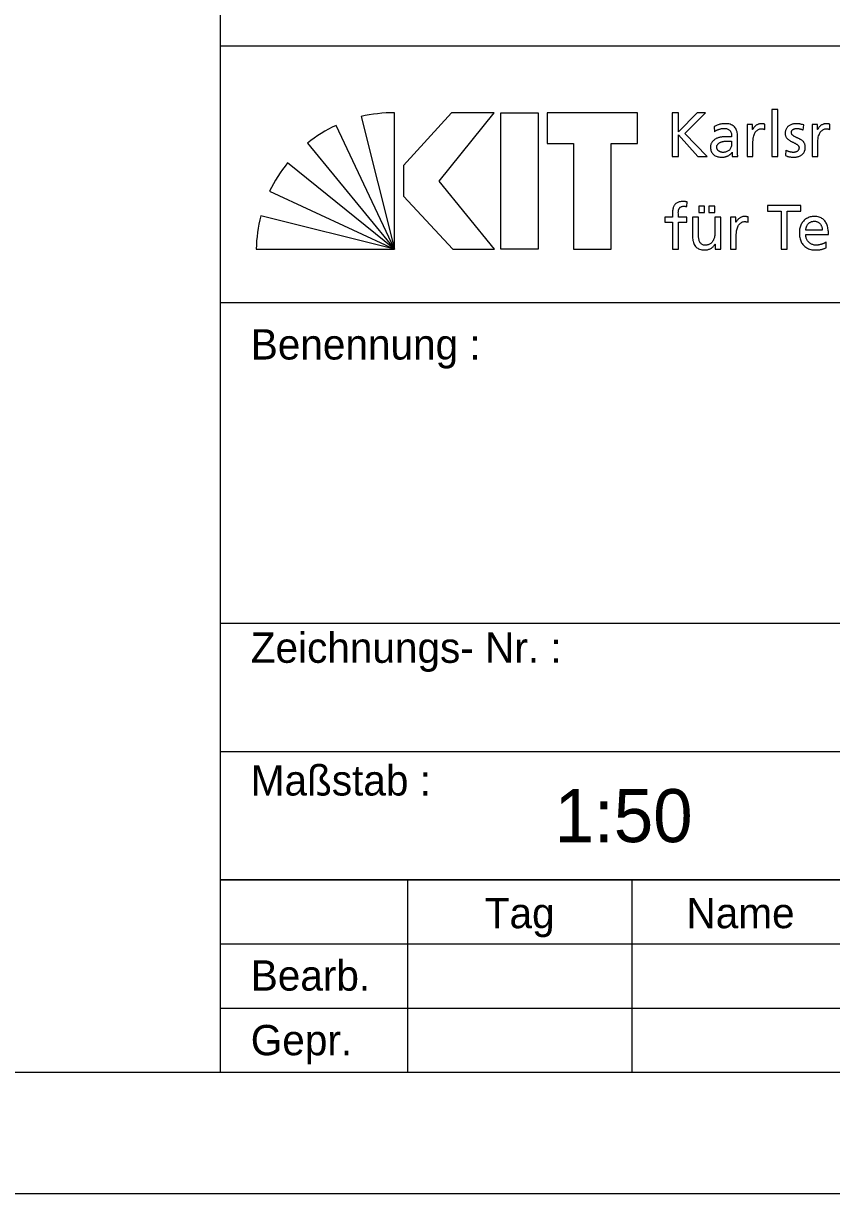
# Model space of a CAD drawing. Extents: x 0 to 21, y 0 to 14.9.
# Drawn here: x 15.75 to 18.416, y 0 to 3.858 of the extents above; entities that cross this region are included whole.
import ezdxf

# ---------------------------------------------------------------- set-up
doc = ezdxf.new("R2010")
doc.units = 0
doc.layers.add('90_Plankopf', color=7, linetype='Continuous')

msp = doc.modelspace()

# ---------------------------------------------------------------- linework, layer by layer
at = {"layer": '90_Plankopf'}
for p, q in [((16.4001, 3.784), (16.4001, 4.4185)), ((16.4001, 3.784), (20.6001, 3.784)), ((16.8638, 3.5511), (16.9741, 3.1138)), ((16.9741, 3.1138), (16.9741, 3.5637)), ((17.8905, 3.5638), (17.8905, 3.4198)), ((16.9741, 3.1138), (16.7817, 3.5221)), ((18.029, 3.5176), (18.03, 3.5011)), ((18.1964, 3.5087), (18.1964, 3.5261)), ((18.3229, 3.5065), (18.3245, 3.5234)), ((18.4106, 3.5087), (18.4106, 3.5261)), ((18.106, 3.4404), (18.106, 3.484)), ((16.6872, 3.4638), (16.9741, 3.1138)), ((18.0866, 3.4699), (18.0866, 3.4606)), ((18.2649, 3.4404), (18.2639, 3.4231)), ((16.9741, 3.1138), (16.6217, 3.3988)), ((17.8905, 3.4198), (17.9112, 3.4198)), ((17.9753, 3.4198), (18.0055, 3.4198)), ((16.562, 3.3052), (16.9741, 3.1138)), ((17.9387, 3.2541), (17.9395, 3.2698)), ((16.9741, 3.1138), (16.5329, 3.2239)), ((18.1414, 3.2027), (18.1414, 3.2201)), ((18.3854, 3.1765), (18.3309, 3.1765)), ((18.3309, 3.1621), (18.406, 3.1621)), ((18.3979, 3.1182), (18.3979, 3.1375)), ((16.5183, 3.1138), (16.9741, 3.1138)), ((16.4001, 2.938), (20.6001, 2.938)), ((16.4001, 1.8805), (20.6001, 1.8805)), ((16.4001, 1.4575), (20.6001, 1.4575)), ((16.4001, 1.0345), (20.6001, 1.0345)), ((16.4001, 1.0345), (20.6001, 1.0345)), ((16.4001, 1.0345), (20.6001, 1.0345)), ((16.4001, 1.0345), (20.6001, 1.0345)), ((16.4001, 0.4), (16.4001, 1.0345)), ((17.0177, 1.0345), (17.0177, 0.4)), ((17.7589, 0.4), (17.7589, 1.0345)), ((16.4001, 0.823), (18.5001, 0.823)), ((16.4001, 0.6115), (18.5001, 0.6115)), ((16.4001, 0.4), (20.6001, 0.4)), ((16.4001, 0.4), (20.6, 0.4))]:
    msp.add_line(p, q, dxfattribs=at)
for points in [[(0, 0), (21, 0), (21, 14.85), (0, 14.85)], [(0.4, 0.4), (20.6, 0.4), (20.6, 14.45), (0.4, 14.45)], [(17.3034, 3.5638), (17.1619, 3.5638), (17.0037, 3.3894), (17.0037, 3.2891), (17.1669, 3.1138), (17.3043, 3.1138), (17.1212, 3.3376)], [(17.4486, 3.5638), (17.4486, 3.1138), (17.3251, 3.1138), (17.3251, 3.5638)], [(17.4782, 3.5638), (17.4782, 3.4625), (17.5651, 3.4625), (17.5651, 3.1138), (17.6886, 3.1138), (17.6886, 3.4625), (17.7755, 3.4625), (17.7755, 3.5638)]]:
    msp.add_lwpolyline(points, close=True, dxfattribs=at)
for points in [[(16.4001, 1.0345), (16.4001, 3.784)], [(18.0055, 3.4198), (17.9324, 3.4957), (18.0001, 3.5638), (17.9726, 3.5638), (17.9112, 3.5005), (17.9112, 3.5638), (17.8905, 3.5638)], [(18.2191, 3.4198), (18.2385, 3.4198), (18.2385, 3.5745), (18.2191, 3.5745), (18.2191, 3.4198)], [(18.1561, 3.5087), (18.1557, 3.5087), (18.1557, 3.525), (18.1376, 3.525), (18.1376, 3.4198), (18.157, 3.4198), (18.157, 3.4677)], [(18.3704, 3.5087), (18.37, 3.5087), (18.37, 3.525), (18.3518, 3.525), (18.3518, 3.4198), (18.3712, 3.4198), (18.3712, 3.4677)], [(17.9112, 3.4198), (17.9112, 3.4904), (17.9753, 3.4198)], [(18.0882, 3.4334), (18.0886, 3.4334), (18.0886, 3.4198), (18.1068, 3.4198)], [(17.9778, 3.2558), (17.9778, 3.2351), (17.9972, 3.2351), (17.9972, 3.2558), (17.9778, 3.2558)], [(18.0116, 3.2558), (18.0116, 3.2351), (18.031, 3.2351), (18.031, 3.2558), (18.0116, 3.2558)], [(18.2496, 3.1138), (18.2702, 3.1138), (18.2702, 3.2397), (18.315, 3.2397), (18.315, 3.2578), (18.2048, 3.2578), (18.2048, 3.2397), (18.2496, 3.2397), (18.2496, 3.1138)], [(17.8913, 3.2288), (17.8913, 3.2191), (17.8665, 3.2191), (17.8665, 3.2034), (17.8913, 3.2034), (17.8913, 3.1138), (17.9107, 3.1138), (17.9107, 3.2034), (17.9385, 3.2034), (17.9385, 3.2191), (17.9107, 3.2191), (17.9107, 3.2304)], [(17.9771, 3.1646), (17.9771, 3.2191), (17.9577, 3.2191), (17.9577, 3.1565)], [(18.0508, 3.1138), (18.0508, 3.2191), (18.0314, 3.2191), (18.0314, 3.1704)], [(18.1012, 3.2027), (18.1008, 3.2027), (18.1008, 3.2191), (18.0826, 3.2191), (18.0826, 3.1138), (18.102, 3.1138), (18.102, 3.1617)], [(18.0316, 3.1305), (18.032, 3.1305), (18.032, 3.1138), (18.0508, 3.1138)], [(20.6001, 1.0345), (16.4001, 1.0345)], [(16.4001, 1.0345), (16.4001, 1.0345)], [(16.4001, 0.4), (20.6001, 0.4)]]:
    msp.add_lwpolyline(points, dxfattribs=at)
for centre, start, end in [((16.9725, 3.0873), 89.8053, 103.1895), ((16.9831, 3.0904), 115.0126, 128.3968), ((16.9909, 3.0976), 140.7898, 154.174), ((16.9946, 3.1064), 165.7222, 179.1064)]:
    msp.add_arc(centre, 0.4764, start, end, dxfattribs=at)
for points in [[(18.106, 3.484), (18.106, 3.4935), (18.1046, 3.5015), (18.1017, 3.508), (18.0988, 3.5145), (18.0942, 3.5193), (18.088, 3.5226), (18.0818, 3.5258), (18.0737, 3.5275), (18.0637, 3.5275), (18.057, 3.5275), (18.0507, 3.5265), (18.0449, 3.5247), (18.0391, 3.5229), (18.0338, 3.5206), (18.029, 3.5176)], [(18.03, 3.5011), (18.0327, 3.5033), (18.0357, 3.5052), (18.039, 3.5068), (18.0423, 3.5084), (18.0459, 3.5096), (18.0495, 3.5105), (18.0532, 3.5114), (18.0569, 3.5118), (18.0606, 3.5118), (18.067, 3.5118), (18.0721, 3.5108), (18.0759, 3.5088), (18.0798, 3.5067), (18.0825, 3.5036), (18.0841, 3.4996), (18.0858, 3.4955), (18.0866, 3.4904), (18.0866, 3.4844)], [(18.1964, 3.5261), (18.195, 3.5263), (18.1937, 3.5266), (18.1925, 3.5268), (18.1913, 3.527), (18.1899, 3.5272), (18.1885, 3.5273), (18.1871, 3.5274), (18.1855, 3.5275), (18.1836, 3.5275), (18.1798, 3.5275), (18.1762, 3.5267), (18.1726, 3.5251), (18.1691, 3.5235), (18.1659, 3.5213), (18.1631, 3.5184), (18.1602, 3.5156), (18.1579, 3.5124), (18.1561, 3.5087)], [(18.3245, 3.5234), (18.3208, 3.5245), (18.3169, 3.5255), (18.313, 3.5263), (18.3091, 3.5271), (18.3049, 3.5275), (18.3004, 3.5275), (18.2952, 3.5275), (18.2903, 3.5268), (18.2858, 3.5255), (18.2813, 3.5242), (18.2774, 3.5222), (18.274, 3.5195), (18.2707, 3.5168), (18.268, 3.5135), (18.2661, 3.5094), (18.2643, 3.5053), (18.2633, 3.5006), (18.2633, 3.4951), (18.2633, 3.4909), (18.2642, 3.4873), (18.2658, 3.4842), (18.2674, 3.4811), (18.2696, 3.4785), (18.2723, 3.4762), (18.275, 3.474), (18.278, 3.472), (18.2812, 3.4702), (18.2844, 3.4685), (18.2877, 3.4669), (18.2909, 3.4654), (18.2942, 3.4638), (18.2971, 3.4622), (18.2998, 3.4606), (18.3025, 3.459), (18.3047, 3.4572), (18.3064, 3.4551), (18.308, 3.4531), (18.3088, 3.4508), (18.3089, 3.4481), (18.3088, 3.4452), (18.3082, 3.4429), (18.307, 3.4409), (18.3058, 3.439), (18.3043, 3.4374), (18.3023, 3.4363), (18.3003, 3.4351), (18.2982, 3.4343), (18.2959, 3.4338), (18.2936, 3.4332), (18.2913, 3.433), (18.2891, 3.433), (18.2871, 3.433), (18.2848, 3.4333), (18.282, 3.4338), (18.2792, 3.4344), (18.2763, 3.4352), (18.2733, 3.4363), (18.2703, 3.4374), (18.2675, 3.4388), (18.2649, 3.4404)], [(18.2639, 3.4231), (18.2684, 3.4208), (18.273, 3.4192), (18.2779, 3.4184), (18.2828, 3.4176), (18.2878, 3.4172), (18.2928, 3.4173), (18.2975, 3.4173), (18.3021, 3.418), (18.3064, 3.4193), (18.3108, 3.4206), (18.3147, 3.4226), (18.3182, 3.4253), (18.3216, 3.428), (18.3244, 3.4314), (18.3264, 3.4355), (18.3284, 3.4396), (18.3295, 3.4445), (18.3295, 3.4501), (18.3295, 3.4549), (18.3286, 3.459), (18.327, 3.4623), (18.3253, 3.4656), (18.3232, 3.4685), (18.3205, 3.4708), (18.3178, 3.4731), (18.3148, 3.4751), (18.3115, 3.4767), (18.3083, 3.4784), (18.3051, 3.4799), (18.3018, 3.4813), (18.2986, 3.4828), (18.2956, 3.4843), (18.2929, 3.4858), (18.2902, 3.4874), (18.2881, 3.4892), (18.2864, 3.4913), (18.2848, 3.4934), (18.2839, 3.496), (18.2839, 3.499), (18.2839, 3.5019), (18.2848, 3.5043), (18.2865, 3.5062), (18.2882, 3.5081), (18.2905, 3.5095), (18.2933, 3.5104), (18.296, 3.5114), (18.2991, 3.5118), (18.3025, 3.5118), (18.3036, 3.5118), (18.3052, 3.5116), (18.307, 3.5114), (18.3088, 3.5111), (18.3107, 3.5106), (18.3128, 3.5101), (18.3148, 3.5096), (18.3167, 3.5091), (18.3185, 3.5084), (18.3203, 3.5078), (18.3218, 3.5071), (18.3229, 3.5065)], [(18.4106, 3.5261), (18.4093, 3.5263), (18.408, 3.5266), (18.4068, 3.5268), (18.4055, 3.527), (18.4042, 3.5272), (18.4028, 3.5273), (18.4014, 3.5274), (18.3997, 3.5275), (18.3978, 3.5275), (18.3941, 3.5275), (18.3904, 3.5267), (18.3869, 3.5251), (18.3834, 3.5235), (18.3802, 3.5213), (18.3773, 3.5184), (18.3744, 3.5156), (18.3721, 3.5124), (18.3704, 3.5087)], [(18.0866, 3.4844), (18.0841, 3.4845), (18.0817, 3.4846), (18.0795, 3.4846), (18.0773, 3.4847), (18.0752, 3.4848), (18.073, 3.4848), (18.0708, 3.4848), (18.0685, 3.4848), (18.0659, 3.4848), (18.0619, 3.4848), (18.0576, 3.4844), (18.0532, 3.4837), (18.0487, 3.483), (18.0443, 3.4818), (18.0401, 3.4802), (18.0358, 3.4786), (18.032, 3.4764), (18.0285, 3.4737), (18.025, 3.4711), (18.0223, 3.4678), (18.0202, 3.4639), (18.0181, 3.46), (18.0171, 3.4554), (18.017, 3.4501), (18.0171, 3.4425), (18.0188, 3.4363), (18.022, 3.4314), (18.0253, 3.4266), (18.0298, 3.423), (18.0355, 3.4207), (18.0413, 3.4184), (18.048, 3.4173), (18.0556, 3.4173), (18.0601, 3.4173), (18.064, 3.4179), (18.0676, 3.4189), (18.0711, 3.42), (18.0742, 3.4213), (18.0769, 3.4229), (18.0796, 3.4246), (18.0818, 3.4264), (18.0837, 3.4282), (18.0856, 3.43), (18.0871, 3.4317), (18.0882, 3.4334)], [(18.157, 3.4677), (18.157, 3.4765), (18.1582, 3.4841), (18.1605, 3.4905), (18.1629, 3.4969), (18.1662, 3.5019), (18.1705, 3.5053), (18.1748, 3.5088), (18.1798, 3.5105), (18.1856, 3.5106), (18.1873, 3.5106), (18.1891, 3.5105), (18.1909, 3.5102), (18.1928, 3.5099), (18.1946, 3.5094), (18.1964, 3.5087)], [(18.3712, 3.4677), (18.3712, 3.4765), (18.3724, 3.4841), (18.3748, 3.4905), (18.3772, 3.4969), (18.3805, 3.5019), (18.3847, 3.5053), (18.389, 3.5088), (18.3941, 3.5105), (18.3999, 3.5106), (18.4016, 3.5106), (18.4033, 3.5105), (18.4052, 3.5102), (18.407, 3.5099), (18.4088, 3.5094), (18.4106, 3.5087)], [(18.0866, 3.4606), (18.0866, 3.4554), (18.0855, 3.4506), (18.0832, 3.4465), (18.081, 3.4423), (18.0777, 3.4391), (18.0734, 3.4367), (18.0691, 3.4343), (18.0637, 3.433), (18.0573, 3.433), (18.055, 3.433), (18.0528, 3.4334), (18.0505, 3.4341), (18.0482, 3.4348), (18.0461, 3.4359), (18.0441, 3.4374), (18.0422, 3.4388), (18.0407, 3.4406), (18.0395, 3.4427), (18.0383, 3.4449), (18.0377, 3.4473), (18.0377, 3.4501), (18.0377, 3.4538), (18.0387, 3.4569), (18.0405, 3.4594), (18.0422, 3.4618), (18.0446, 3.4638), (18.0475, 3.4652), (18.0504, 3.4667), (18.0535, 3.4678), (18.0568, 3.4686), (18.0601, 3.4693), (18.0633, 3.4698), (18.0664, 3.47), (18.0694, 3.4703), (18.072, 3.4704), (18.0742, 3.4703), (18.0762, 3.4703), (18.0783, 3.4703), (18.0804, 3.4701), (18.0824, 3.47), (18.0845, 3.47), (18.0866, 3.4699)], [(18.1068, 3.4198), (18.1066, 3.4208), (18.1065, 3.4222), (18.1064, 3.4238), (18.1063, 3.4256), (18.1062, 3.4278), (18.1061, 3.4305), (18.106, 3.4331), (18.106, 3.4365), (18.106, 3.4404)], [(17.9395, 3.2698), (17.9376, 3.2701), (17.9356, 3.2704), (17.9334, 3.2707), (17.9313, 3.2709), (17.929, 3.2711), (17.9265, 3.2711), (17.9194, 3.271), (17.9136, 3.27), (17.9089, 3.2681), (17.9043, 3.2661), (17.9007, 3.2632), (17.8982, 3.2595), (17.8956, 3.2558), (17.8938, 3.2513), (17.8928, 3.2461), (17.8917, 3.241), (17.8912, 3.2352), (17.8913, 3.2288)], [(17.9107, 3.2304), (17.9106, 3.234), (17.9108, 3.2373), (17.9112, 3.2403), (17.9117, 3.2433), (17.9125, 3.246), (17.9138, 3.2482), (17.9151, 3.2505), (17.917, 3.2522), (17.9195, 3.2535), (17.922, 3.2547), (17.9253, 3.2554), (17.9294, 3.2554), (17.9311, 3.2554), (17.9328, 3.2553), (17.9345, 3.2551), (17.9361, 3.2548), (17.9376, 3.2545), (17.9387, 3.2541)], [(18.1414, 3.2201), (18.1401, 3.2204), (18.1387, 3.2206), (18.1376, 3.2208), (18.1363, 3.221), (18.135, 3.2212), (18.1335, 3.2213), (18.1322, 3.2215), (18.1305, 3.2215), (18.1286, 3.2215), (18.1249, 3.2215), (18.1212, 3.2207), (18.1177, 3.2191), (18.1142, 3.2175), (18.111, 3.2153), (18.1081, 3.2125), (18.1052, 3.2097), (18.1029, 3.2064), (18.1012, 3.2027)], [(18.102, 3.1617), (18.102, 3.1705), (18.1032, 3.1782), (18.1056, 3.1846), (18.1079, 3.191), (18.1112, 3.1959), (18.1155, 3.1993), (18.1198, 3.2028), (18.1249, 3.2046), (18.1307, 3.2046), (18.1324, 3.2046), (18.1341, 3.2045), (18.136, 3.2042), (18.1378, 3.204), (18.1396, 3.2035), (18.1414, 3.2027)], [(18.406, 3.1621), (18.406, 3.1706), (18.4052, 3.1785), (18.4037, 3.1857), (18.4021, 3.1929), (18.3995, 3.1991), (18.3959, 3.2045), (18.3923, 3.2099), (18.3876, 3.214), (18.3816, 3.217), (18.3756, 3.22), (18.3683, 3.2215), (18.3595, 3.2215), (18.3521, 3.2215), (18.3453, 3.2202), (18.3393, 3.2176), (18.3333, 3.215), (18.3281, 3.2114), (18.3237, 3.2066), (18.3194, 3.2019), (18.3161, 3.1963), (18.3138, 3.1897), (18.3114, 3.1833), (18.3103, 3.1761), (18.3102, 3.1683), (18.3102, 3.1597), (18.3113, 3.1519), (18.3135, 3.1449), (18.3157, 3.138), (18.319, 3.132), (18.3235, 3.127), (18.3279, 3.122), (18.3336, 3.1181), (18.3404, 3.1154), (18.3473, 3.1127), (18.3554, 3.1114), (18.3647, 3.1113), (18.3704, 3.1114), (18.3753, 3.1118), (18.3794, 3.1125), (18.3834, 3.1133), (18.3869, 3.1142), (18.3899, 3.1152), (18.3928, 3.1162), (18.3955, 3.1172), (18.3979, 3.1182)], [(18.3309, 3.1765), (18.3312, 3.18), (18.332, 3.1834), (18.3332, 3.1869), (18.3344, 3.1903), (18.3362, 3.1934), (18.3384, 3.1963), (18.3407, 3.1992), (18.3435, 3.2015), (18.3469, 3.2032), (18.3503, 3.2049), (18.3544, 3.2058), (18.3591, 3.2058), (18.3633, 3.2058), (18.367, 3.2051), (18.3703, 3.2035), (18.3735, 3.202), (18.3763, 3.1999), (18.3785, 3.1972), (18.3807, 3.1946), (18.3824, 3.1914), (18.3836, 3.1879), (18.3848, 3.1844), (18.3854, 3.1806), (18.3854, 3.1765)], [(18.0314, 3.1704), (18.0314, 3.1639), (18.0308, 3.1581), (18.0295, 3.1528), (18.0282, 3.1475), (18.0263, 3.1429), (18.0237, 3.1391), (18.0211, 3.1352), (18.0177, 3.1323), (18.0137, 3.1302), (18.0097, 3.1281), (18.0049, 3.1271), (17.9994, 3.127), (17.9938, 3.1274), (17.9894, 3.1289), (17.9861, 3.1318), (17.9828, 3.1346), (17.9805, 3.1387), (17.9791, 3.1442), (17.9778, 3.1496), (17.9771, 3.1564), (17.9771, 3.1646)], [(17.9577, 3.1565), (17.9577, 3.1471), (17.9591, 3.139), (17.9619, 3.1323), (17.9647, 3.1255), (17.969, 3.1204), (17.9748, 3.1168), (17.9806, 3.1132), (17.9881, 3.1114), (17.9972, 3.1113), (18.0021, 3.1114), (18.0068, 3.1121), (18.0113, 3.1136), (18.0158, 3.1152), (18.0198, 3.1174), (18.0234, 3.1202), (18.0269, 3.1231), (18.0296, 3.1265), (18.0316, 3.1305)], [(18.3979, 3.1375), (18.3967, 3.1366), (18.395, 3.1355), (18.3927, 3.1342), (18.3904, 3.133), (18.3878, 3.1319), (18.3848, 3.1308), (18.3818, 3.1297), (18.3786, 3.1288), (18.3753, 3.1281), (18.372, 3.1274), (18.3688, 3.1271), (18.3655, 3.127), (18.3609, 3.1271), (18.3565, 3.1279), (18.3524, 3.1296), (18.3482, 3.1313), (18.3445, 3.1337), (18.3413, 3.1368), (18.3381, 3.1399), (18.3355, 3.1435), (18.3337, 3.1478), (18.3319, 3.1521), (18.3309, 3.1569), (18.3309, 3.1621)]]:
    msp.add_open_spline(points, degree=3, dxfattribs=at)

# ---------------------------------------------------------------- texts
for s, height, p in [('Benennung :', 0.1, (16.5001, 2.75)), ('Zeichnungs- Nr. :', 0.1, (16.5001, 1.75)), ('Maßstab :', 0.1, (16.5001, 1.3125)), ('1:50    ', 0.175, (17.5024, 1.1587)), ('Tag', 0.1, (17.2721, 0.875)), ('Name', 0.1, (17.9376, 0.875)), ('Bearb.', 0.1, (16.5001, 0.6692)), ('Gepr.', 0.1, (16.5001, 0.4561))]:
    msp.add_text(s, height=height, dxfattribs=at).set_placement(p)

doc.saveas('drawing.dxf')
